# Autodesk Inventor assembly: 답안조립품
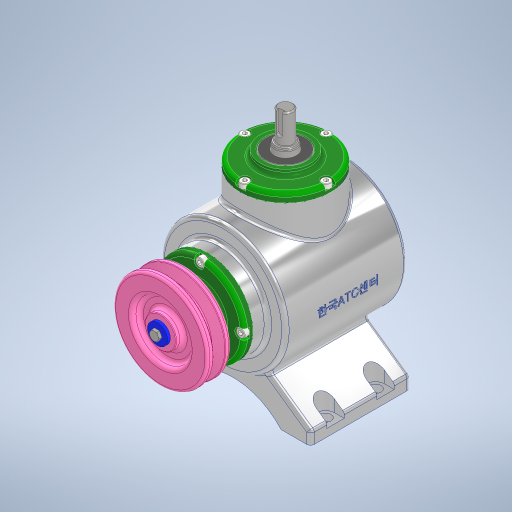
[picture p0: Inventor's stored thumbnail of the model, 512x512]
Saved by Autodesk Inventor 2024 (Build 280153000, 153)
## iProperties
Created: 2023-08
Part Number: 답안조립품
Document SubType Name: Assembly
Designer: Owner
Author: Owner
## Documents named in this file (17)
- C:\Users\Owner\Desktop\730813V1014\답안조립품.iam
- C:\Users\Owner\Desktop\730813V1014\본체.ipt
- C:\Users\Owner\Desktop\730813V1014\V-벨트풀리.ipt
- C:\Users\Owner\Desktop\730813V1014\메인 베벨기어.ipt
- C:\Users\Owner\Desktop\730813V1014\메인 축.ipt
- 메인 축.ipt
- C:\Users\Owner\Desktop\730813V1014\베어링 6203.ipt
- C:\Users\Owner\Desktop\730813V1014\볼트 M4 x 10.ipt
- C:\Users\Owner\Desktop\730813V1014\서브 베벨기어.ipt
- C:\Users\Owner\Desktop\730813V1014\서브 축.ipt
- 서브 축.ipt
- C:\Users\Owner\Desktop\730813V1014\오일실 17 x 32 x 8.ipt
- C:\Users\Owner\Desktop\730813V1014\와셔 4 x 16.ipt
- C:\Users\Owner\Desktop\730813V1014\육각볼트 M4 x 8.ipt
- C:\Users\Owner\Desktop\730813V1014\커버.ipt
- C:\Users\Owner\Desktop\730813V1014\키 4 x 4 x 14.ipt
- C:\Users\Owner\Desktop\730813V1014\키 5 x 5 x 14.ipt
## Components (1 placed, 1 different names)
1. V-벨트풀리:1 — 플러쉬:5
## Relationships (1: Flush 1)
- 플러쉬:5 [Flush]: V-벨트풀리:1
